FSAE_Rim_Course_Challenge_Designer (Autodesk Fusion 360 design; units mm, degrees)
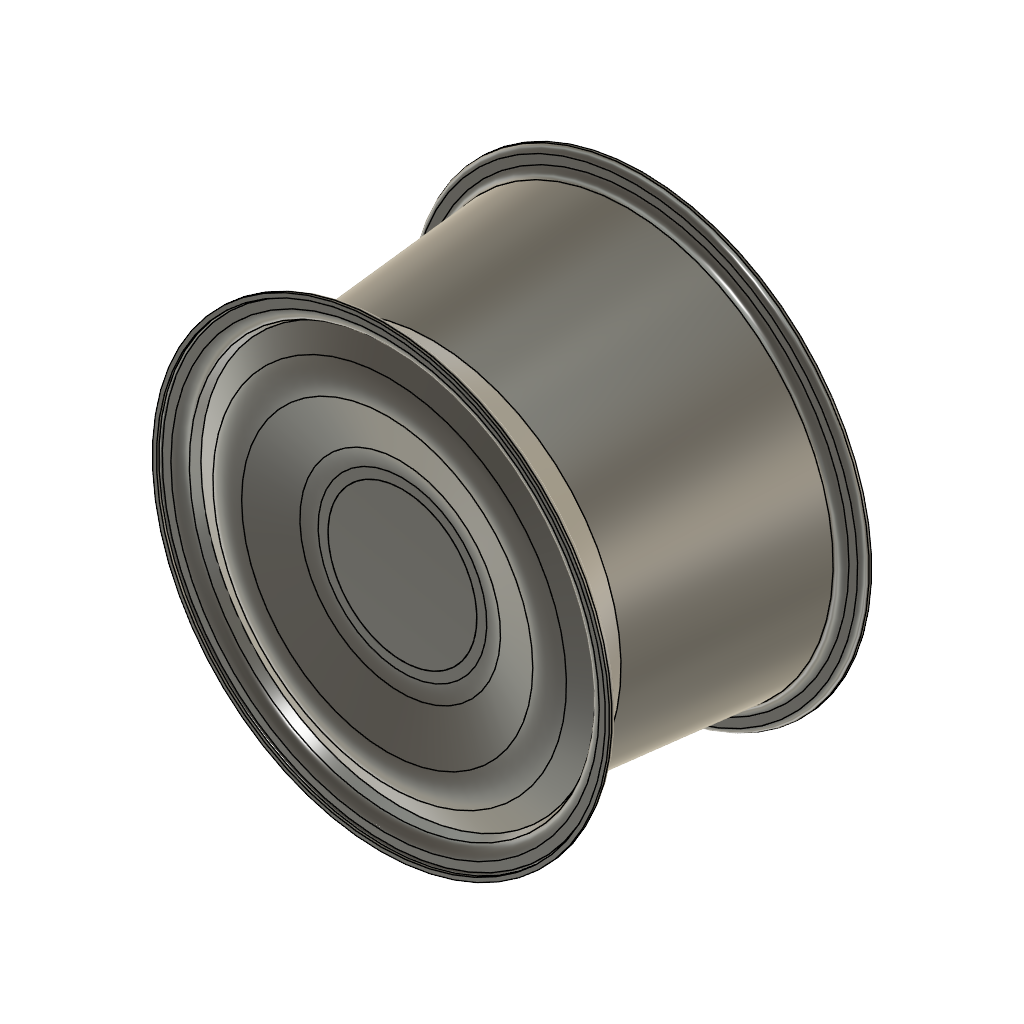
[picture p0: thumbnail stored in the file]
part number: 2026-07-27-09-56-27-671
sketch "Sketch1" plane through (0, 0, 0) normal (1, 0, 0) x axis (0, 1, 0)
  line L1 (153.5, 0) -> (0, 0)
  line L2 (0, 119.5) -> (0, 104)
  line L3 (143.5, 124.5) -> (5, 124.5)
  line L4 (148.5, 134.75) -> (148.5, 129.5)
  line L5 (153.5, 138.25) -> (152, 138.25)
  line L6 (2.5, 119.5) -> (2.5, 104)
  line L7 (143.5, 122) -> (5, 122)
  line L8 (151, 134.75) -> (151, 129.5)
  line L9 (153.5, 135.75) -> (152, 135.75)
  line L10 (2.5, 104) -> (0, 104)
  line L11 (153.5, 135.75) -> (153.5, 138.25)
  arc A1 centre (152, 134.75) radius 3.5 clockwise from (148.5, 134.75) to (152, 138.25)
  arc A2 centre (143.5, 129.5) radius 5 clockwise from (148.5, 129.5) to (143.5, 124.5)
  arc A3 centre (5, 119.5) radius 5 clockwise from (0, 119.5) to (5, 124.5)
  arc A4 centre (5, 119.5) radius 2.5 clockwise from (2.5, 119.5) to (5, 122)
  arc A5 centre (143.5, 129.5) radius 7.5 clockwise from (151, 129.5) to (143.5, 122)
  arc A6 centre (152, 134.75) radius 1 clockwise from (151, 134.75) to (152, 135.75)
  point P1 (0, 0)
  point P2 (0, 0)
  point P4 (0, 104)
  point P3 (153.5, 0)
  point P7 (153.5, 138.25)
  point P6 (148.5, 124.5)
  point P5 (0, 124.5)
  coincident P1 P2
  horizontal L1
  perpendicular L1 L2
  perpendicular L2 L3
  perpendicular L3 L4
  perpendicular L4 L5
  vertical P1 P4
  vertical P3 P7
  tangent L4 A1
  tangent L5 A1
  coincident P6 L3
  coincident P6 L4
  tangent L3 A2
  tangent L4 A2
  coincident P5 L2
  coincident P5 L3
  tangent L2 A3
  tangent L3 A3
  equal A2 A3
  perpendicular L6 L10
  perpendicular L9 L11
  dimension "d1" distance P2 P3 = 153.5
  dimension "d2" = 208
  dimension "d3" = 249
  dimension "d4" = 276.5
  dimension "d5" distance P5 P6 = 148.5
  dimension "d6" radius A1 = 3.5
  dimension "d7" radius A2 = 5
  dimension "d8" = 2.5
revolve "Revolve1" sketch "Sketch1" AlongAngle 360 bodies "FSAE Rim Back"
sketch "Sketch2" plane through (0, 0, 0) normal (0, -1, 0) x axis (1, 0, 0)
  circle C1 centre (0, 0) radius 104
  circle C2 centre (0, 0) radius 119.5
  circle C3 centre (0, 0) radius 112
  circle C4 centre (0, 112) radius 2.15
  point P1 (0, 0)
  point P3 (0, 0)
  point P4 (0, 112)
  coincident P1 P3
  coincident C3 P4
  vertical P3 P4
  dimension "d10" diameter C3 = 224
  dimension "d11" diameter C4 = 4.3
extrude "Extrude1" cut sketch "Sketch2" profile of C4 to an object
circular_pattern "C-Pattern1" TotalAngle 360
canvas "Canvas1"
move "Move1"
sketch "Sketch4" plane through (0, 0, 0) normal (1, 0, 0) x axis (0, 1, 0)
  line L1 (39.5755, 0) -> (0, 0)
  line L2 (144, 138.25) -> (145.5, 138.25)
  line L3 (140.5, 129.5) -> (140.5, 134.75)
  line L4 (-3, 124.5) -> (135.5, 124.5)
  line L5 (135.5, 122) -> (-3, 122)
  line L6 (143, 134.75) -> (143, 129.5)
  line L7 (145.5, 135.75) -> (144, 135.75)
  line L8 (145.5, 138.25) -> (145.5, 135.75)
  line L9 (66.25, 141.2695) -> (66.25, 124.5)
  line L10 (-10.5, 134.75) -> (-10.5, 129.5)
  line L11 (-13, 135.75) -> (-11.5, 135.75)
  line L12 (-13, 138.25) -> (-13, 135.75)
  line L13 (-11.5, 138.25) -> (-13, 138.25)
  line L14 (-8, 129.5) -> (-8, 134.75)
  line L15 (17.5319, 111.6505) -> (-6.1696, 122.7027)
  line L16 (136.1537, 122.0285) -> (17.5319, 111.6505)
  line L17 (17.9813, 114.1994) -> (-5.1131, 124.9685)
  line L18 (135.9358, 124.519) -> (17.9813, 114.1994)
  line L19 (0, 45) -> (0, 0)
  line L20 (15, 45) -> (0, 45)
  line L21 (15, 0) -> (15, 45)
  line L22 (-7.7219, 106.8759) -> (-1.3827, 120.4705)
  line L23 (-1.3558, 60.6473) -> (-9.2057, 88.023)
  line L24 (0, 45) -> (0, 51)
  line L25 (4.3158, 103.6873) -> (7.6804, 116.2443)
  line L26 (15, 45) -> (15, 63)
  line L27 (15, 63) -> (5.7602, 84.2501)
  arc A1 centre (144, 134.75) radius 3.5 clockwise from (140.5, 134.75) to (144, 138.25)
  arc A2 centre (135.5, 129.5) radius 5 between (135.5, 124.5) and (140.5, 129.5)
  arc A3 centre (135.5, 129.5) radius 7.5 clockwise from (143, 129.5) to (135.5, 122)
  arc A4 centre (144, 134.75) radius 1 between (144, 135.75) and (143, 134.75)
  arc A5 centre (-3, 129.5) radius 7.5 clockwise from (-3, 122) to (-10.5, 129.5)
  arc A6 centre (-11.5, 134.75) radius 1 between (-10.5, 134.75) and (-11.5, 135.75)
  arc A7 centre (-11.5, 134.75) radius 3.5 clockwise from (-11.5, 138.25) to (-8, 134.75)
  arc A8 centre (-3, 129.5) radius 5 between (-8, 129.5) and (-3, 124.5)
  arc A9 centre (16.7484, 95.4652) radius 27 clockwise from (-9.2057, 88.023) to (-7.7219, 106.8759)
  arc A10 centre (32.8678, 96.0368) radius 29.5592 clockwise from (5.7602, 84.2501) to (4.3158, 103.6873)
  arc A11 centre (-35, 51) radius 35 clockwise from (-1.3558, 60.6473) to (0, 51)
  point P1 (0, 0)
  point P2 (0, 0)
  point P18 (66.25, 124.5)
  point P4 (145.5, 138.25)
  point P27 (-13, 138.25)
  point P5 (144, 138.25)
  point P28 (-11.5, 138.25)
  point P6 (140.5, 134.75)
  point P29 (-8, 134.75)
  point P8 (140.5, 129.5)
  point P30 (-8, 129.5)
  point P9 (135.5, 124.5)
  point P31 (-3, 124.5)
  point P13 (135.5, 122)
  point P21 (-3, 122)
  point P14 (143, 129.5)
  point P22 (-10.5, 129.5)
  point P15 (143, 134.75)
  point P23 (-10.5, 134.75)
  point P16 (144, 135.75)
  point P25 (-11.5, 135.75)
  point P17 (145.5, 135.75)
  point P26 (-13, 135.75)
  point P32 (-6.1696, 122.7027)
  point P34 (136.1537, 122.0285)
  point P35 (-5.1131, 124.9685)
  point P37 (135.9358, 124.519)
  point P40 (15, 0)
  point P41 (-1.3827, 120.4705)
  point P45 (7.6804, 116.2443)
  point P38 (0, 45)
  point P46 (4.3158, 103.6873)
  point P42 (-7.7219, 106.8759)
  point P39 (15, 45)
  point P49 (15, 63)
  point P51 (0, 51)
  coincident P1 P2
  horizontal L1
  midpoint L4 P18
  perpendicular L5 L9
  symmetric P4 L9 P27
  symmetric P5 L9 P28
  symmetric P6 L9 P29
  symmetric A1 L9 A7
  symmetric P8 L9 P30
  symmetric P9 L9 P31
  symmetric A2 L9 A8
  symmetric P13 L9 P21
  symmetric P14 L9 P22
  symmetric A3 L9 A5
  symmetric P15 L9 P23
  symmetric P16 L9 P25
  symmetric A4 L9 A6
  symmetric P17 L9 P26
  coincident A5 P32
  tangent A5 L15
  coincident A3 P34
  tangent A3 L16
  coincident A8 P35
  tangent A8 L17
  coincident A2 P37
  tangent A2 L18
  parallel L16 L18
  parallel L15 L17
  perpendicular L1 L19
  perpendicular L19 L20
  coincident L1 P40
  perpendicular L1 L21
  coincident L15 P41
  perpendicular L15 L22
  tangent L22 A9
  tangent A9 L23
  vertical L24
  coincident L15 P45
  tangent L25 A10
  vertical L26
  tangent L23 A11
  tangent L24 A11
  tangent A10 L27
  dimension "d66" angle L5 L15 = 25
  dimension "d67" angle L5 L16 = 5
  dimension "d68" distance P41 P45 = 10
  dimension "d69" angle L22 L25 = 10
  dimension "d70" radius A11 = 35
  dimension "d71" distance L19 L21 = 15
  dimension "d72" distance P2 P38 = 45
  dimension "d73" distance P45 P46 = 13
  dimension "d74" distance P41 P42 = 15
  dimension "d75" radius A9 = 27
  dimension "d76" distance P39 P49 = 18
  dimension "d77" angle L23 L27 = 7.5
  dimension "d78" angle L26 L27 = 23.5
  dimension "d79" distance P38 P51 = 6
revolve "Revolve4" sketch "Sketch4" AlongAngle 360 bodies "Barrel", "Hub"
revolve "Revolve5" sketch "Sketch4" AlongAngle 360 bodies "Spokes"
remove_body "RemoveBody1"
named bodies: "FSAE Rim Back", "Barrel", "Hub", "Spokes"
